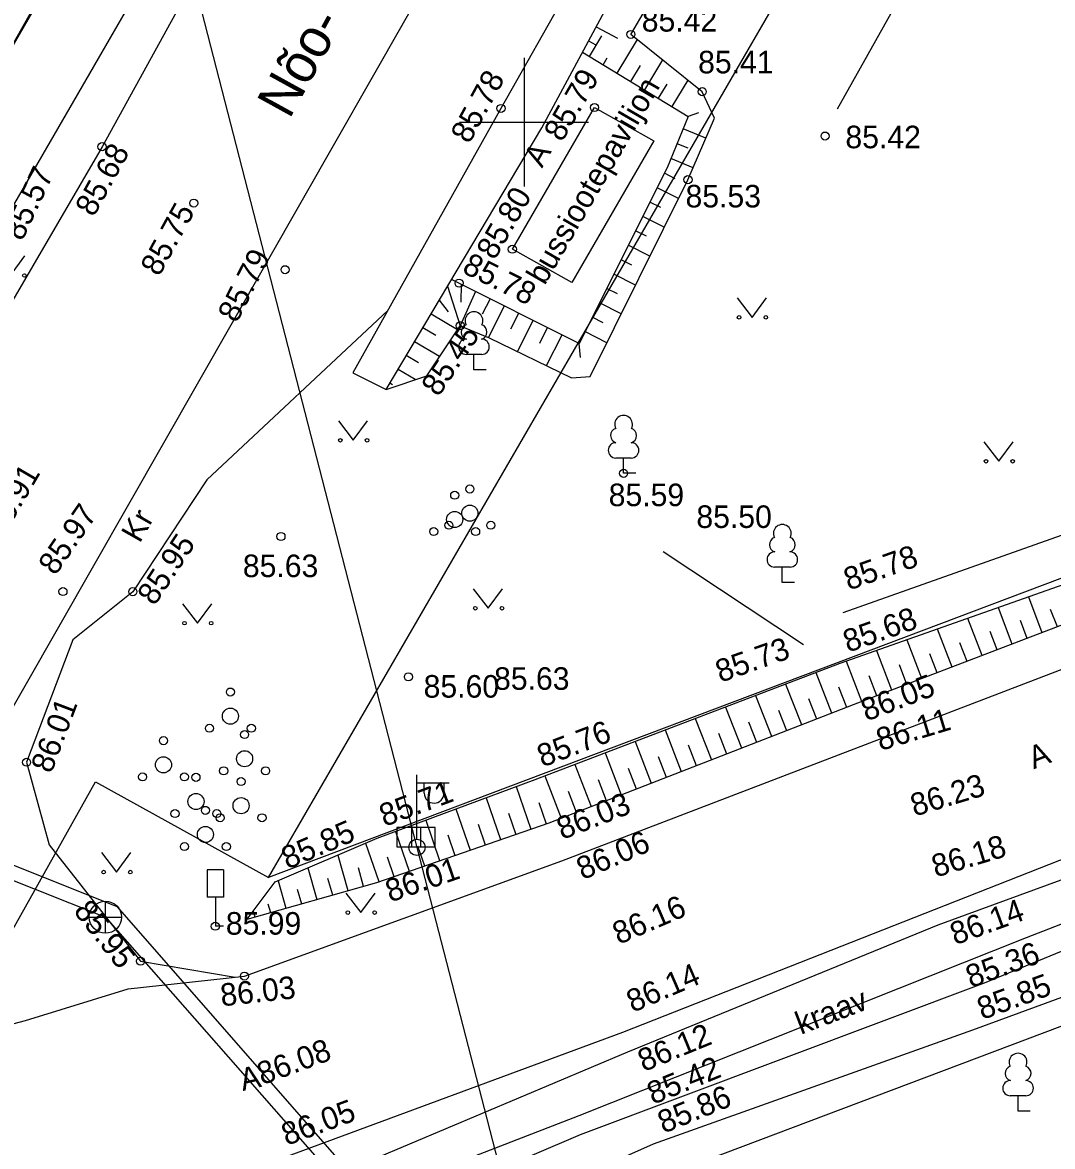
# Model space of a CAD drawing. Extents: x 648748 to 649126, y 6457789 to 6458252.
# Drawn here: x 648884.43 to 648916.41, y 6458118.21 to 6458153.1 of the extents above; entities that cross this region are included whole.
import ezdxf

# ---------------------------------------------------------------- set-up
doc = ezdxf.new("R2010")
doc.units = 0
for name, color, linetype in [('ELRAJATISMP', 7, 'Continuous'), ('HALJASTUS', 7, 'Continuous'), ('KKAEV', 7, 'Continuous'), ('KORGUS-EH2000', 7, 'Continuous'), ('KTRASS', 7, 'Continuous'), ('LIIKLUS', 7, 'Continuous'), ('MPOHULIIN', 7, 'Continuous'), ('PIIR', 7, 'Continuous'), ('POST', 7, 'Continuous'), ('PUU', 7, 'Continuous'), ('RAJATIS', 7, 'Continuous'), ('RELJEEF', 7, 'Continuous'), ('SITRASS', 7, 'Continuous'), ('SKTRASS', 7, 'Continuous'), ('TEE', 7, 'Continuous'), ('VEEKOGU', 7, 'Continuous'), ('VORK', 7, 'Continuous'), ('VTRASS', 7, 'Continuous')]:
    doc.layers.add(name, color=color, linetype=linetype)

msp = doc.modelspace()

# ---------------------------------------------------------------- linework, layer by layer
at = {"layer": 'ELRAJATISMP'}
for p, q in [((648897.243, 6458128.104), (648896.048, 6458128.104)), ((648896.048, 6458128.104), (648896.048, 6458127.507)), ((648896.51, 6458128.104), (648896.51, 6458127.507)), ((648896.781, 6458128.104), (648896.781, 6458127.507)), ((648897.243, 6458127.507), (648897.243, 6458128.104)), ((648896.048, 6458127.507), (648897.243, 6458127.507))]:
    msp.add_line(p, q, dxfattribs=at)
at = {"layer": 'HALJASTUS'}
for p, q in [((648884.058, 6458145.243), (648884.504, 6458145.85)), ((648906.614, 6458144.548), (648907.078, 6458143.942)), ((648907.078, 6458143.942), (648907.523, 6458144.548)), ((648894.236, 6458140.733), (648894.699, 6458140.126)), ((648894.699, 6458140.126), (648895.145, 6458140.733)), ((648914.279, 6458140.08), (648914.742, 6458139.474)), ((648914.742, 6458139.474), (648915.188, 6458140.08)), ((648908.672, 6458133.782), (648904.319, 6458136.664)), ((648898.424, 6458135.521), (648898.887, 6458134.914)), ((648898.887, 6458134.914), (648899.333, 6458135.521)), ((648889.396, 6458135.055), (648889.86, 6458134.449)), ((648889.86, 6458134.449), (648890.305, 6458135.055)), ((648886.883, 6458127.33), (648887.347, 6458126.724)), ((648887.347, 6458126.724), (648887.792, 6458127.33)), ((648894.468, 6458126.074), (648894.932, 6458125.467)), ((648894.932, 6458125.467), (648895.377, 6458126.074))]:
    msp.add_line(p, q, dxfattribs=at)
msp.add_lwpolyline([(648924.28, 6458139.819), (648919.338, 6458138.114), (648909.894, 6458134.773)], dxfattribs=at)
for centre in [(648884.486, 6458145.243), (648906.677, 6458143.942), (648907.506, 6458143.942), (648894.298, 6458140.126), (648895.127, 6458140.126), (648914.341, 6458139.474), (648915.17, 6458139.474), (648898.486, 6458134.914), (648899.315, 6458134.914), (648889.459, 6458134.449), (648890.288, 6458134.449), (648886.946, 6458126.724), (648887.775, 6458126.724), (648894.531, 6458125.467), (648895.36, 6458125.467)]:
    msp.add_circle(centre, 0.055, dxfattribs=at)
at = {"layer": 'KKAEV'}
for p, q in [((648887.002, 6458124.824), (648887.002, 6458125.824)), ((648886.502, 6458125.324), (648887.502, 6458125.324))]:
    msp.add_line(p, q, dxfattribs=at)
msp.add_circle((648887.002, 6458125.324), 0.5, dxfattribs=at)
at = {"layer": 'KORGUS-EH2000'}
for centre in [(648903.317, 6458152.725), (648905.534, 6458150.948), (648899.284, 6458150.429), (648902.188, 6458150.455), (648909.346, 6458149.571), (648886.897, 6458149.241), (648905.09, 6458148.216), (648889.746, 6458147.489), (648899.637, 6458146.056), (648892.58, 6458145.422), (648897.983, 6458145.004), (648898.022, 6458143.684), (648903.091, 6458139.102), (648892.453, 6458137.141), (648885.685, 6458135.433), (648887.855, 6458135.428), (648896.412, 6458132.785), (648884.556, 6458130.133), (648890.416, 6458125.042), (648888.093, 6458123.958), (648891.319, 6458123.494)]:
    msp.add_circle(centre, 0.125, dxfattribs=at)
at = {"layer": 'KTRASS'}
for p, q in [((648866.552, 6458133.483), (648887.002, 6458125.324)), ((648887.002, 6458125.324), (648899.409, 6458111.226))]:
    msp.add_line(p, q, dxfattribs=at)
at = {"layer": 'LIIKLUS'}
for points in [[(648890.166, 6458126.792), (648890.166, 6458125.942)], [(648890.666, 6458126.792), (648890.166, 6458126.792)], [(648890.666, 6458126.792), (648890.666, 6458125.942)], [(648890.666, 6458125.942), (648890.166, 6458125.942)], [(648890.416, 6458125.942), (648890.416, 6458125.042)], [(648890.666, 6458125.042), (648890.416, 6458125.042)]]:
    msp.add_lwpolyline(points, dxfattribs=at)
at = {"layer": 'MPOHULIIN'}
msp.add_lwpolyline([(648879.733, 6458193.241), (648887.677, 6458162.414), (648896.676, 6458127.492), (648901.112, 6458110.279), (648910.288, 6458074.678)], dxfattribs=at)
at = {"layer": 'PIIR'}
for p, q in [((648892.07, 6458126.56), (648909.45, 6458156.56)), ((648945.9, 6458146.87), (648892.07, 6458126.56)), ((648895.06, 6458113.79), (648952.09, 6458135.31)), ((648874.11, 6458107.05), (648886.69, 6458129.53)), ((648886.69, 6458129.53), (648892.07, 6458126.56))]:
    msp.add_line(p, q, dxfattribs=at)
at = {"layer": 'POST'}
for p, q in [((648896.676, 6458127.742), (648896.676, 6458129.742)), ((648896.676, 6458129.492), (648897.676, 6458129.492)), ((648896.902, 6458129.171), (648896.902, 6458129.492)), ((648897.515, 6458129.171), (648897.515, 6458129.492))]:
    msp.add_line(p, q, dxfattribs=at)
msp.add_circle((648896.676, 6458127.492), 0.25, dxfattribs=at)
msp.add_arc((648897.209, 6458129.171), 0.306, 180, 0, dxfattribs=at)
at = {"layer": 'PUU'}
for p, q in [((648898.686, 6458142.794), (648898.206, 6458142.794)), ((648898.446, 6458142.319), (648898.446, 6458142.794)), ((648898.826, 6458142.319), (648898.446, 6458142.319)), ((648903.331, 6458139.577), (648902.851, 6458139.577)), ((648903.091, 6458139.102), (648903.091, 6458139.577)), ((648903.471, 6458139.102), (648903.091, 6458139.102)), ((648908.259, 6458136.19), (648907.779, 6458136.19)), ((648908.019, 6458135.715), (648908.019, 6458136.19)), ((648908.399, 6458135.715), (648908.019, 6458135.715)), ((648915.577, 6458119.779), (648915.097, 6458119.779)), ((648915.337, 6458119.304), (648915.337, 6458119.779)), ((648915.717, 6458119.304), (648915.337, 6458119.304))]:
    msp.add_line(p, q, dxfattribs=at)
msp.add_lwpolyline([(648909.729, 6458150.414), (648912.112, 6458154.671), (648912.882, 6458157.584)], dxfattribs=at)
for centre, radius in [((648898.318, 6458138.615), 0.125), ((648897.847, 6458138.42), 0.125), ((648898.318, 6458137.865), 0.25), ((648897.668, 6458137.49), 0.125), ((648897.847, 6458137.67), 0.25), ((648898.968, 6458137.49), 0.125), ((648897.197, 6458137.295), 0.125), ((648898.497, 6458137.295), 0.125), ((648890.883, 6458132.313), 0.125), ((648890.883, 6458131.563), 0.25), ((648890.233, 6458131.188), 0.125), ((648891.533, 6458131.188), 0.125), ((648891.324, 6458130.992), 0.125), ((648888.805, 6458130.804), 0.125), ((648888.805, 6458130.054), 0.25), ((648891.324, 6458130.242), 0.25), ((648890.674, 6458129.867), 0.125), ((648891.974, 6458129.867), 0.125), ((648888.155, 6458129.679), 0.125), ((648889.455, 6458129.679), 0.125), ((648889.814, 6458129.665), 0.125), ((648891.215, 6458129.535), 0.125), ((648889.814, 6458128.915), 0.25), ((648891.215, 6458128.785), 0.25), ((648889.164, 6458128.54), 0.125), ((648890.107, 6458128.64), 0.125), ((648890.464, 6458128.54), 0.125), ((648890.565, 6458128.41), 0.125), ((648891.865, 6458128.41), 0.125), ((648890.107, 6458127.89), 0.25), ((648889.457, 6458127.515), 0.125), ((648890.757, 6458127.515), 0.125)]:
    msp.add_circle(centre, radius, dxfattribs=at)
for centre, radius, start, end in [((648898.446, 6458143.839), 0.277, 332.58, 207.42), ((648898.276, 6458143.491), 0.233, 109.022, 253.142), ((648898.616, 6458143.491), 0.233, 286.851, 70.986), ((648898.209, 6458143.031), 0.238, 90.002, 269.395), ((648898.684, 6458143.031), 0.238, 270.605, 89.998), ((648903.091, 6458140.622), 0.277, 332.58, 207.42), ((648902.921, 6458140.275), 0.233, 109.022, 253.142), ((648903.261, 6458140.275), 0.233, 286.851, 70.986), ((648902.853, 6458139.815), 0.238, 90.002, 269.395), ((648903.328, 6458139.815), 0.238, 270.605, 89.998), ((648908.019, 6458137.235), 0.277, 332.58, 207.42), ((648907.849, 6458136.888), 0.233, 109.022, 253.142), ((648908.189, 6458136.888), 0.233, 286.851, 70.986), ((648907.782, 6458136.428), 0.238, 90.002, 269.395), ((648908.257, 6458136.428), 0.238, 270.605, 89.998), ((648915.337, 6458120.824), 0.277, 332.58, 207.42), ((648915.167, 6458120.477), 0.233, 109.022, 253.142), ((648915.507, 6458120.477), 0.233, 286.851, 70.986), ((648915.1, 6458120.017), 0.238, 90.002, 269.395), ((648915.575, 6458120.017), 0.238, 270.605, 89.998)]:
    msp.add_arc(centre, radius, start, end, dxfattribs=at)
at = {"layer": 'RAJATIS'}
msp.add_lwpolyline([(648899.637, 6458146.056), (648902.188, 6458150.455), (648904.029, 6458149.426), (648901.479, 6458145.027), (648899.637, 6458146.056)], dxfattribs=at)
at = {"layer": 'RELJEEF'}
for p, q in [((648902.241, 6458152.965), (648902.902, 6458152.61)), ((648902.028, 6458152.041), (648902.417, 6458152.682)), ((648902.004, 6458152.525), (648902.224, 6458152.406)), ((648903.516, 6458152.566), (648902.882, 6458151.522)), ((648902.455, 6458151.782), (648902.585, 6458151.995)), ((648904.303, 6458151.935), (648903.737, 6458151.003)), ((648903.61, 6458151.756), (648903.31, 6458151.263)), ((648905.09, 6458151.304), (648904.592, 6458150.484)), ((648904.43, 6458151.181), (648904.164, 6458150.743)), ((648905.421, 6458150.294), (648905.094, 6458150.179)), ((648905.649, 6458149.507), (648904.938, 6458149.797)), ((648905.1, 6458149.191), (648904.75, 6458149.334)), ((648905.252, 6458148.589), (648904.561, 6458148.871)), ((648904.691, 6458148.247), (648904.359, 6458148.414)), ((648904.8, 6458147.633), (648904.134, 6458147.967)), ((648904.244, 6458147.353), (648903.91, 6458147.52)), ((648904.355, 6458146.738), (648903.686, 6458147.074)), ((648903.797, 6458146.458), (648903.461, 6458146.627)), ((648903.909, 6458145.842), (648903.237, 6458146.18)), ((648903.35, 6458145.564), (648903.013, 6458145.733)), ((648903.464, 6458144.947), (648902.789, 6458145.286)), ((648898.051, 6458144.97), (648898.035, 6458144.416)), ((648897.623, 6458144.906), (648898.022, 6458143.684)), ((648898.498, 6458144.746), (648898.022, 6458143.684)), ((648902.903, 6458144.669), (648902.564, 6458144.839)), ((648897.368, 6458144.476), (648897.648, 6458144.116)), ((648898.945, 6458144.521), (648898.705, 6458144.044)), ((648898.898, 6458143.313), (648899.392, 6458144.297)), ((648903.019, 6458144.052), (648902.34, 6458144.392)), ((648897.936, 6458143.556), (648897.112, 6458144.046)), ((648899.593, 6458143.585), (648899.839, 6458144.073)), ((648902.456, 6458143.775), (648902.116, 6458143.946)), ((648897.257, 6458143.378), (648896.856, 6458143.617)), ((648899.799, 6458142.879), (648900.285, 6458143.848)), ((648900.491, 6458143.143), (648900.732, 6458143.624)), ((648897.378, 6458142.724), (648896.6, 6458143.187)), ((648900.699, 6458142.444), (648901.179, 6458143.4)), ((648902.573, 6458143.156), (648901.891, 6458143.499)), ((648901.758, 6458142.698), (648901.708, 6458143.134)), ((648896.722, 6458142.533), (648896.345, 6458142.757)), ((648896.622, 6458142.01), (648896.089, 6458142.328)), ((648895.916, 6458141.849), (648895.833, 6458141.898)), ((648915.66, 6458135.268), (648916.08, 6458134.166)), ((648914.716, 6458134.935), (648915.146, 6458133.809)), ((648916.34, 6458134.889), (648916.548, 6458134.344)), ((648913.773, 6458134.602), (648914.212, 6458133.453)), ((648915.401, 6458134.545), (648915.613, 6458133.988)), ((648912.83, 6458134.27), (648913.278, 6458133.096)), ((648914.462, 6458134.2), (648914.679, 6458133.631)), ((648911.886, 6458133.937), (648912.343, 6458132.739)), ((648913.523, 6458133.855), (648913.745, 6458133.274)), ((648910.943, 6458133.604), (648911.409, 6458132.383)), ((648912.584, 6458133.511), (648912.811, 6458132.918)), ((648909.999, 6458133.272), (648910.475, 6458132.026)), ((648911.645, 6458133.166), (648911.876, 6458132.561)), ((648909.055, 6458132.917), (648909.543, 6458131.665)), ((648910.707, 6458132.821), (648910.942, 6458132.204)), ((648908.121, 6458132.561), (648908.611, 6458131.302)), ((648909.765, 6458132.471), (648910.008, 6458131.846)), ((648907.186, 6458132.205), (648907.679, 6458130.939)), ((648908.832, 6458132.111), (648909.077, 6458131.483)), ((648906.252, 6458131.848), (648906.747, 6458130.576)), ((648907.899, 6458131.752), (648908.145, 6458131.121)), ((648905.317, 6458131.492), (648905.815, 6458130.213)), ((648906.966, 6458131.392), (648907.213, 6458130.758)), ((648904.383, 6458131.136), (648904.883, 6458129.851)), ((648906.033, 6458131.033), (648906.281, 6458130.395)), ((648903.448, 6458130.78), (648903.952, 6458129.488)), ((648905.1, 6458130.673), (648905.349, 6458130.032)), ((648902.514, 6458130.424), (648903.02, 6458129.125)), ((648904.166, 6458130.313), (648904.417, 6458129.669)), ((648901.579, 6458130.067), (648902.088, 6458128.762)), ((648903.233, 6458129.954), (648903.486, 6458129.306)), ((648900.645, 6458129.711), (648901.156, 6458128.399)), ((648902.3, 6458129.594), (648902.554, 6458128.943)), ((648899.76, 6458129.38), (648900.216, 6458128.058)), ((648901.367, 6458129.235), (648901.622, 6458128.58)), ((648898.823, 6458129.031), (648899.271, 6458127.732)), ((648900.459, 6458128.887), (648900.689, 6458128.221)), ((648897.885, 6458128.683), (648898.326, 6458127.406)), ((648899.517, 6458128.55), (648899.744, 6458127.895)), ((648896.947, 6458128.334), (648897.38, 6458127.08)), ((648898.576, 6458128.213), (648898.798, 6458127.569)), ((648896.01, 6458127.986), (648896.435, 6458126.753)), ((648897.634, 6458127.876), (648897.853, 6458127.243)), ((648895.078, 6458127.619), (648895.49, 6458126.427)), ((648896.693, 6458127.538), (648896.908, 6458126.916)), ((648894.217, 6458127.25), (648894.529, 6458126.151)), ((648895.752, 6458127.201), (648895.962, 6458126.59)), ((648893.29, 6458126.853), (648893.567, 6458125.878)), ((648894.845, 6458126.868), (648895.01, 6458126.287)), ((648892.363, 6458126.455), (648892.605, 6458125.604)), ((648893.9, 6458126.533), (648894.048, 6458126.014)), ((648892.956, 6458126.198), (648893.086, 6458125.741)), ((648892.047, 6458125.74), (648892.124, 6458125.468)), ((648891.591, 6458125.513), (648891.643, 6458125.331))]:
    msp.add_line(p, q, dxfattribs=at)
for points in [[(648895.718, 6458141.704), (648896.98, 6458142.131), (648898.022, 6458143.684), (648898.915, 6458143.306), (648901.478, 6458142.068), (648902.049, 6458142.102), (648905.09, 6458148.216), (648905.916, 6458150.124), (648905.534, 6458150.948), (648903.317, 6458152.725), (648905.259, 6458156.04), (648906.264, 6458158.745), (648907.202, 6458162.117), (648908.197, 6458164.225)], [(648901.814, 6458152.171), (648905.094, 6458150.179), (648904.444, 6458148.584), (648901.708, 6458143.134), (648897.751, 6458145.12)], [(648891.402, 6458125.263), (648892.278, 6458126.419), (648895.437, 6458127.773), (648900.348, 6458129.598), (648909.816, 6458133.207), (648921.057, 6458137.171), (648925.663, 6458138.565), (648930.796, 6458140.499), (648936.472, 6458142.392), (648941.646, 6458144.685), (648943.957, 6458145.386), (648945.119, 6458145.311)], [(648891.402, 6458125.263), (648895.428, 6458126.406), (648900.776, 6458128.251), (648910.226, 6458131.931), (648921.515, 6458136.241), (648925.907, 6458137.896), (648931.321, 6458139.756), (648936.899, 6458141.409), (648941.788, 6458143.605), (648945.119, 6458145.311)]]:
    msp.add_lwpolyline(points, dxfattribs=at)
at = {"layer": 'SITRASS'}
for points in [[(648929.925, 6458240.085), (648929.233, 6458238.833), (648926.729, 6458233.327), (648923.21, 6458225.506), (648918.966, 6458215.361), (648917.027, 6458210.342), (648911.341, 6458199.533), (648902.157, 6458183.584), (648896.992, 6458174.764), (648890.118, 6458163.377), (648888.523, 6458160), (648880.878, 6458146.779), (648876.372, 6458138.998), (648873.186, 6458136.533), (648872.398, 6458135.159), (648870.194, 6458131.921), (648868.778, 6458129.583), (648863.975, 6458121.708)], [(648863.975, 6458121.708), (648868.963, 6458118.276), (648873.908, 6458114.787), (648879.921, 6458111.046), (648881.11, 6458110.63), (648883.242, 6458110.955), (648895.055, 6458116.596), (648901.713, 6458119.167), (648915.597, 6458124.69), (648933.55, 6458131.654), (648947.17, 6458136.394), (648958.488, 6458140.137), (648967.592, 6458140.769)]]:
    msp.add_lwpolyline(points, dxfattribs=at)
at = {"layer": 'SKTRASS'}
msp.add_lwpolyline([(648864.925, 6458092.31), (648866.693, 6458094.618), (648870.108, 6458099.799), (648873.651, 6458103.509), (648877.881, 6458106.787), (648884.142, 6458110.459), (648889.114, 6458113.182), (648901.758, 6458118.582), (648914.292, 6458123.291), (648928.272, 6458129.024), (648937.137, 6458131.944), (648947.113, 6458135.218)], dxfattribs=at)
at = {"layer": 'TEE'}
for points in [[(648891.319, 6458123.494), (648901.175, 6458127.077), (648933.887, 6458139.607), (648944.575, 6458143.741), (648947.822, 6458145.717), (648948.882, 6458147.636), (648949.478, 6458151.73), (648949.531, 6458156.617), (648950.372, 6458161.859), (648951.909, 6458167.68), (648954.505, 6458172.94), (648956.528, 6458180.218), (648952.525, 6458185.448), (648945.526, 6458192.898), (648938.29, 6458202.321), (648932.248, 6458208.399), (648929.676, 6458210.569), (648928.257, 6458209.969), (648926.047, 6458207.531), (648924.786, 6458206.368), (648922.091, 6458200.973), (648909.112, 6458176.906), (648898.467, 6458156.964), (648883.402, 6458130.595)], [(648910.613, 6458192.21), (648903.667, 6458179.751), (648902.811, 6458178.379), (648900.807, 6458174.931), (648897.151, 6458176.001), (648894.164, 6458177.881), (648892.628, 6458174.223), (648892.59, 6458172.02), (648894.122, 6458172.629), (648896.444, 6458172.027), (648898.105, 6458170.013), (648896.987, 6458167.363), (648892.71, 6458159.787), (648886.897, 6458149.241), (648880.501, 6458138.274)], [(648894.686, 6458142.224), (648895.718, 6458141.704), (648900.554, 6458149.829), (648904.623, 6458157.392), (648903.572, 6458157.964), (648903.52, 6458157.93)], [(648903.52, 6458157.93), (648899.284, 6458150.429), (648894.686, 6458142.224)], [(648964.651, 6458078.174), (648966.451, 6458083.821), (648967.5, 6458089.655), (648970.461, 6458102.422), (648972.022, 6458109.308), (648974.38, 6458121.59), (648976.218, 6458132.059), (648976.233, 6458135.434), (648975.702, 6458138.304), (648974.226, 6458140.713), (648971.86, 6458143.333), (648969.445, 6458145.153), (648966.422, 6458144.919), (648958.871, 6458143.041), (648949.896, 6458140.146), (648946.296, 6458138.815), (648935.488, 6458134.684), (648924.063, 6458130.013), (648903.056, 6458121.74), (648892.363, 6458117.796), (648888.636, 6458116.575), (648879.911, 6458112.582)], [(648895.767, 6458144.154), (648890.156, 6458138.9), (648887.855, 6458135.428), (648885.99, 6458133.93), (648884.556, 6458130.133), (648885.259, 6458127.566), (648888.093, 6458123.958), (648891.035, 6458123.463)], [(648881.434, 6458121.312), (648884.526, 6458122.113), (648887.705, 6458123.098), (648891.319, 6458123.494)]]:
    msp.add_lwpolyline(points, dxfattribs=at)
at = {"layer": 'VEEKOGU'}
for points in [[(648894.824, 6458171.369), (648894.188, 6458170.423), (648893.695, 6458169.558), (648890.688, 6458164.197), (648885.8, 6458155.403), (648881.852, 6458148.408), (648881.551, 6458147.775), (648882.109, 6458147.118), (648882.61, 6458146.464), (648883.683, 6458146.633), (648888.008, 6458154.101), (648892.53, 6458163.125), (648895.927, 6458168.395), (648896.425, 6458169.506), (648896.234, 6458170.624), (648896.101, 6458171.13)], [(648881.501, 6458110.34), (648886.47, 6458113.521), (648891.938, 6458116.388), (648903.218, 6458121.14), (648912.855, 6458125.083), (648924.425, 6458129.317), (648935.909, 6458133.554), (648937.278, 6458129.638), (648925.712, 6458126.147), (648913.923, 6458121.814), (648904.01, 6458118.277), (648893.604, 6458113.65), (648888.243, 6458110.763), (648882.29, 6458107.188)]]:
    msp.add_lwpolyline(points, dxfattribs=at)
at = {"layer": 'VORK'}
for p, q in [((648900, 6458152), (648900, 6458148)), ((648898, 6458150), (648902, 6458150))]:
    msp.add_line(p, q, dxfattribs=at)
at = {"layer": 'VTRASS'}
msp.add_lwpolyline([(648859.612, 6458137.039), (648866.748, 6458133.902), (648887.357, 6458125.656), (648899.553, 6458111.732), (648928.544, 6458121.558), (648956.932, 6458132.595), (648957.558, 6458132.798), (648975.434, 6458138.594), (648975.797, 6458138.798), (648976.302, 6458139.082)], dxfattribs=at)

# ---------------------------------------------------------------- texts
at = {"layer": 'KORGUS-EH2000'}
for s, p in [('85.42', (648903.655, 6458152.813)), ('85.41', (648905.405, 6458151.516)), ('85.42', (648909.978, 6458149.192)), ('85.53', (648905.014, 6458147.355)), ('85.59', (648902.628, 6458138.082)), ('85.50', (648905.351, 6458137.406)), ('85.63', (648891.27, 6458135.88)), ('85.63', (648899.069, 6458132.382)), ('85.60', (648896.883, 6458132.139)), ('85.99', (648890.741, 6458124.782))]:
    msp.add_text(s, height=0.7, dxfattribs=at).set_placement(p)
for s, rotation, p in [('85.78', 61.4254, (648898.3, 6458149.302)), ('85.79', 59.8922, (648901.179, 6458149.358)), ('85.68', 61.136, (648886.64, 6458147.033)), ('85.57', 64.8243, (648884.418, 6458146.282)), ('85.80', 59.8922, (648899.086, 6458145.692)), ('85.75', 61.136, (648888.668, 6458145.184)), ('85.79', 62.9771, (648891.08, 6458143.742)), ('85.78', 333.3469, (648898.041, 6458145.352)), ('85.45', 56.14, (648897.344, 6458141.451)), ('85.91', 59.7476, (648883.819, 6458137.091)), ('85.97', 55.3822, (648885.447, 6458135.902)), ('85.95', 56.469, (648888.528, 6458134.963)), ('85.78', 19.4822, (648910.08, 6458135.459)), ('85.68', 19.4246, (648910.058, 6458133.531)), ('85.73', 19.4246, (648906.098, 6458132.598)), ('86.05', 20.8962, (648910.631, 6458131.396)), ('86.01', 69.3227, (648885.322, 6458129.759)), ('86.11', 16.8367, (648911.062, 6458130.481)), ('85.76', 20.8658, (648900.573, 6458129.969)), ('86.23', 16.8367, (648912.124, 6458128.445)), ('85.71', 20.3858, (648895.668, 6458128.125)), ('86.03', 21.2768, (648901.186, 6458127.719)), ('85.85', 23.2008, (648892.658, 6458126.8)), ('86.06', 23.3272, (648901.821, 6458126.471)), ('86.18', 16.8367, (648912.783, 6458126.552)), ('86.01', 19.0339, (648895.846, 6458125.778)), ('85.95', 308.1501, (648885.989, 6458125.509)), ('86.16', 23.3272, (648902.94, 6458124.463)), ('86.14', 20.0999, (648913.386, 6458124.45)), ('85.36', 20.0999, (648913.873, 6458123.121)), ('86.14', 23.3272, (648903.374, 6458122.353)), ('86.03', 6.2596, (648890.609, 6458122.555)), ('85.85', 20.0999, (648914.228, 6458122.131)), ('86.12', 22.252, (648903.714, 6458120.516)), ('86.08', 20.246, (648891.874, 6458120.107)), ('85.42', 22.252, (648904.003, 6458119.497)), ('85.86', 22.252, (648904.331, 6458118.602)), ('86.05', 20.246, (648892.63, 6458118.224))]:
    msp.add_text(s, height=0.7, rotation=rotation, dxfattribs=at).set_placement(p)
at = {"layer": 'RAJATIS'}
msp.add_text('bussiootepaviljon', height=0.7, rotation=59.8922, dxfattribs=at).set_placement((648900.641, 6458144.915))
at = {"layer": 'TEE'}
for s, height, rotation, p in [('Nõo-Tamsa tee', 1.2, 61.136, (648892.714, 6458150.069)), ('A', 0.7, 60.3302, (648900.559, 6458148.558)), ('Kr', 0.7, 60.3302, (648888.067, 6458136.909)), ('A', 0.7, 21.3517, (648915.826, 6458129.914)), ('A', 0.7, 13.0428, (648891.267, 6458119.925))]:
    msp.add_text(s, height=height, rotation=rotation, dxfattribs=at).set_placement(p)
at = {"layer": 'VEEKOGU'}
msp.add_text('kraav', height=0.7, rotation=21.013, dxfattribs=at).set_placement((648908.593, 6458121.671))

doc.saveas('drawing.dxf')
